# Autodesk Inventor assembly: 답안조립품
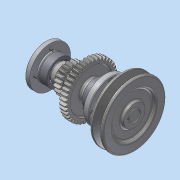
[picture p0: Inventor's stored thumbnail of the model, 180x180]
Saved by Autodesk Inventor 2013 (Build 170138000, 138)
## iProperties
Created: 2016-01
Part Number: 답안조립품
Document SubType Name: Assembly
Designer: Administrator
Author: Administrator
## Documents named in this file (15)
- C:\Users\Administrator\Desktop\460106V1011\답안조립품.iam
- C:\Users\Administrator\Desktop\460106V1011\본체.ipt
- C:\Users\Administrator\Desktop\460106V1011\앞커버.ipt
- C:\Users\Administrator\Desktop\460106V1011\뒤커버.ipt
- C:\Users\Administrator\Desktop\460106V1011\베어링 6203.ipt
- C:\Users\Administrator\Desktop\460106V1011\부시1.ipt
- C:\Users\Administrator\Desktop\460106V1011\부시2.ipt
- C:\Users\Administrator\Desktop\460106V1011\볼트 M3 x 8.ipt
- C:\Users\Administrator\Desktop\460106V1011\볼트 M3 x 10.ipt
- C:\Users\Administrator\Desktop\460106V1011\축.ipt
- C:\Users\Administrator\Desktop\460106V1011\V-벨트풀리.ipt
- C:\Users\Administrator\Desktop\460106V1011\스퍼기어.ipt
- C:\Users\Administrator\Desktop\460106V1011\오일씰 28 40 8.ipt
- C:\Users\Administrator\Desktop\460106V1011\키 - 6 x 6 x 22.ipt
- C:\Users\Administrator\Desktop\460106V1011\키 - 5 x 5 x 18.ipt
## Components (9 placed, 3 different names)
1. V-벨트풀리:1
2. ISO 4762 M3 x 8:1
3. ISO 4762 M3 x 8:2
4. ISO 4762 M3 x 8:3
5. ISO 4762 M3 x 8:4
6. ISO 4762 M3 x 10:1
7. ISO 4762 M3 x 10:2
8. ISO 4762 M3 x 10:3
9. ISO 4762 M3 x 10:4
